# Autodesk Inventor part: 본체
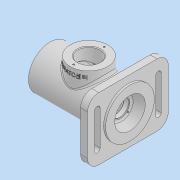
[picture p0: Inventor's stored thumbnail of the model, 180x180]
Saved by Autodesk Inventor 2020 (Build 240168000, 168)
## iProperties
Created: 2021-07
Part Number: 본체
Material: 일반
Document SubType Name: Modeling
Designer: MIRAE
Density: 1 g/cm^3
Appearance: 기본값
Author: MIRAE
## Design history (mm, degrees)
sketch "스케치1"
  geometry: L1 (-58, 45)-(58, 45); L2 (58, 45)-(58, -45); L3 (58, -45)-(-58, -45); L4 (-58, -45)-(-58, 45); L5 (-58, 45)-(58, -45); L6 (58, 45)-(-58, -45); 1 further point
  constraints: 12 end point, 2 midpoint, 2 parallel, 1 horizontal, 1 perpendicular
  dimensions: "d0" = 116 distance of L2.end L3.end; "d1" = 90 distance of L1.end L2.end
extrude "돌출1" new body sketch "스케치1" distance "d2" = 10; taper "d3" = 0 deg
sketch "스케치2"
  geometry: C1 r 35 at (0, 0); 1 further point
  constraints: 1 centre point, 1 coincident
  dimensions: "d4" = 70 diameter of C1
extrude "돌출2" join sketch "스케치2" distance "d5" = 3; taper "d6" = 0 deg
sketch "스케치3"
  geometry: C1 r 35 at (0, 0) reference; C2 r 31 at (0, 0); 1 further point
  constraints: 1 centre point, 1 coincident
  dimensions: "d7" = 62 diameter of C2
extrude "돌출3" join sketch "스케치3" distance "d8" = 102; taper "d9" = 0 deg
sketch "스케치4"
  geometry: L1 (102, -31)-(102, 31) reference; L2 (-13, 35)-(-13, -35) reference; L3 (93, 24)-(90, 24); L4 (90, 24)-(90, 0); L5 (90, 0)-(93, 0); L6 (93, 0)-(93, 24); L7 (90, 20)-(81, 20); L8 (81, 20)-(81, 0); L9 (81, 0)-(90, 0); L10 (90, 0)-(90, 20); L11 (81, 17.5)-(65, 17.5); L12 (65, 17.5)-(65, 0); L13 (65, 0)-(81, 0); L14 (81, 0)-(81, 17.5); L15 (77.75, 18.5)-(76, 18.5); L16 (76, 18.5)-(76, 0); L17 (76, 0)-(77.75, 0); L18 (77.75, 0)-(77.75, 18.5); L19 (65, 26)-(27, 26); L20 (27, 26)-(27, 0); L21 (27, 0)-(65, 0); L22 (65, 0)-(65, 26); L23 (27, 17.5)-(16, 17.5); L24 (16, 17.5)-(16, 0); L25 (16, 0)-(27, 0); L26 (27, 0)-(27, 17.5); L27 (16, 16)-(11, 16); L28 (11, 16)-(11, 0); L29 (11, 0)-(16, 0); L30 (16, 0)-(16, 16); L31 (11, 10)-(8.3, 10); L32 (8.3, 10)-(8.3, 0); L33 (8.3, 0)-(11, 0); L34 (11, 0)-(11, 10); L35 (8.3, 12.5)-(1, 12.5); L36 (1, 12.5)-(1, 0); L37 (1, 0)-(8.3, 0); L38 (8.3, 0)-(8.3, 12.5); L39 (1, 12.5)-(1, 16); L40 (1, 16)-(-13, 22); 8 further points
  constraints: 76 end point, 18 parallel, 9 horizontal, 9 perpendicular, 9 point on line, 2 midpoint, 1 vertical, 11 other
  dimensions: "d10" = 48 dimension on L3; "d11" = 9 distance between parallel lines of L6 L1; "d12" = 3 distance of L3.start L3.end; "d13" = 9 distance of L7.start L7.end; "d14" = 40 dimension on L7; "d15" = 35 dimension on L11; "d16" = 37 dimension on L15; "d17" = 1.75 distance of L15.start L15.end; "d18" = 11 distance between parallel lines of L12 L16; "d20" = 38 distance between parallel lines of L20 L12; "d21" = 65 distance between parallel lines of L24 L14; "d22" = 52 dimension on L19; "d23" = 35 dimension on L23; "d24" = 91 distance between parallel lines of L1 L28; "d25" = 14 distance between parallel lines of L2 L36; "d26" = 20 dimension on L31; "d27" = 32 dimension on L27; "d28" = 25 dimension on L35; "d29" = 7.3 distance between parallel lines of L36 L32; "d30" = 44 dimension on L40.end; "d31" = 32 dimension on L39.end
revolve "회전1" sketch "스케치4" stored, may be unused: angle "d32" = 90 deg
sketch "스케치5"
  geometry: C1 r 10 at (0, 0) reference; 2 further points
  constraints: 1 coincident
hole "구멍1" sketch "스케치5" at (0, 0) diameter "d33" = 40.3762; stored, may be unused: countersink angle "d37" = 90 deg, drill point angle "d39" = 118 deg; dims "d34" = 84, "d35" = 4, "d36" = 2, "d38" = 9
node "작업 평면1"
sketch "스케치6"
  geometry: L1 (0, 58)-(0, -58) reference; L2 (-102, 31)-(-102, -31) reference; C1 r 27 at (-46, 0); 2 further points
  constraints: 1 centre point, 1 horizontal alignment, 1 midpoint
  dimensions: "d41" = 54 diameter of C1; "d42" = 56 distance from line of C1.centre L2
extrude "돌출4" join sketch "스케치6" stored distance "d43" = 102; taper "d44" = 0 deg
sketch "스케치7"
  geometry: C1 r 27 at (0, 0) reference; C2 r 16 at (0, 0); 1 further point
  constraints: 1 centre point, 1 coincident
  dimensions: "d45" = 32 diameter of C2
extrude "돌출5" cut sketch "스케치7" stored distance "d46" = 0; taper "d47" = 0 deg; dims "d49" = 3
fillet "모깎기1" dims "d48" = 16
fillet "모깎기2" dims "d49" = 3
fillet "모깎기3" dims "d50" = 0.3
chamfer "모따기1" distance "d51" = 0.7; stored, may be unused: second distance "d52" = 2, angle "d53" = 30 deg
chamfer "모따기2" distance "d54" = 1; stored, may be unused: second distance "d55" = 2, angle "d56" = 30 deg
chamfer "모따기3" distance "d57" = 1; stored, may be unused: second distance "d58" = 2, angle "d59" = 30 deg
sketch "스케치8"
  geometry: C1 r 27 at (0, 0) reference; 2 further points
  constraints: 1 vertical alignment
  dimensions: "d60" = 22 distance of C1.centre point (0, 22)
hole "구멍2" sketch "스케치8" at (0, 22) diameter "d61" = 2.459; stored, may be unused: countersink angle "d65" = 90 deg, drill point angle "d67" = 118 deg; dims "d62" = 6, "d63" = 4, "d64" = 2, "d66" = 8
sketch "스케치9"
  geometry: L1 (-25, -44)-(25, -44); L2 (-25, -48)-(25, -48); L3 (25, -40)-(-25, -40); C1 r 35 at (0, 0) reference; A1 r 4 centre (-25, -44) between (-25, -40) and (-25, -48); A2 r 4 centre (25, -44) between (25, -48) and (25, -40); 2 further points
  constraints: 8 end point, 4 point on circle, 4 tangent, 2 centre point, 1 horizontal, 1 midpoint, 1 parallel, 1 vertical alignment
  dimensions: "d68" = 44 distance of point (0, -44) point (0, 0); "d69" = 4 radius of A1; "d70" = 50 distance of L1.end L1.start
extrude "돌출6" cut sketch "스케치9" distance "d71" = 102; taper "d72" = 0 deg
node "작업 평면3"
sketch "스케치10"
  geometry: L1 (-19, 42)-(-73, 42) reference; 3 further points
  constraints: 1 midpoint, 1 vertical alignment, 1 other
  dimensions: "d74" = 8 distance from line of L1 point (-46, 34)
sketch "스케치11"
  geometry: 1 further point
feature "엠보싱1" dims "d0" = 116, "d1" = 90, "d75" = 0.5, "d76" = 0
fillet "모깎기4" dims "d77" = 3
sketch "스케치12"
  geometry: 1 further point
sketch "스케치13"
  geometry: L1 (-64.041, 0)-(62.15, 0); L2 (62.15, 0)-(62.15, -69.476); L3 (62.15, -69.476)-(-64.041, -69.476); L4 (-64.041, -69.476)-(-64.041, 0); 1 further point
  constraints: 8 end point, 2 parallel, 1 horizontal, 1 perpendicular
extrude "돌출7" cut sketch "스케치13" extent not by distance; stored distance "d78" = 0; taper "d79" = 0 deg
node "솔리드1"
mirror "미러1"
mirror "미러2"
node "작업 평면2"
feature "A9D066F2-1C7D-4E18-AEED-F7BC21143FA4" dims "d33" = 40.3762, "d34" = 84, "d35" = 4, "d36" = 2, "d37" = 90 deg, "d38" = 9, "d39" = 118 deg
other parameters: "d40" = 42, "d73" = -27
